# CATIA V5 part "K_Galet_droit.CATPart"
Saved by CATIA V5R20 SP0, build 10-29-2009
Part number: Galet_droit
Bounding box of the stored display mesh (mm): x 0 to 17.955, y -11.571 to 11.571, z -11.571 to 11.571
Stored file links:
  G:\Khaled_CFAO_2011\SIL\SIL_GR2\zthiebault\Khaled\CAD_ThinkMOTION\K_Galet_droit.CATPart
  F:\Projet Thinkmotion\Catia\galet.CATPart
  F:\Projet Thinkmotion\Catia\FINAL\HabillageFinal.CATProduct
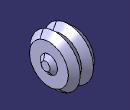
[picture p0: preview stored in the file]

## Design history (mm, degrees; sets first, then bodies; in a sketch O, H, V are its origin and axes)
External parameters (linked from other documents)
  External.Rgaletaucontact = 9 mm
  `External.dist_bâticerclecontactgalet` = 10.41 mm
Set1
  Line1 "Droite_base_galetdroit": linked copy from another document
  Plane1 "Plan_base_galet_cerclecontact": linked copy from another document
Body1 (main body)
  Sketch1 on zx-plane, origin (0, 0, 0), H (-1, 0, 0), V (0, 0, 1)
    line L1 (0, 0) -> (-17.9551, 0)
    line L2 (-17.9551, 0) -> (-17.9551, -2)
    line L3 (-17.9551, -2) -> (-16.41, -3.9654)
    point P4 (-16.41, -3.9654)
    line L4 (-16.41, -3.9654) -> (-16.41, -8.9654)
    line L5 (-16.41, -8.9654) -> (-13.4742, -11.5712)
    line L6 (-13.4742, -11.5712) -> (-10.41, -9)
    point P7 (-10.41, -9)
    line L7 (-10.41, -9) -> (-7.3458, -11.5712)
    line L8 (-7.3458, -11.5712) -> (-4.41, -9)
    line L9 (-4.41, -9) -> (-4.41, -3)
    line L10 (-4.41, -3) -> (-1.3229, -3)
    line L11 (-1.3229, -3) -> (0, -1.5)
    line L12 (0, -1.5) -> (0, 0)
    construction line L13 (-13.4742, -11.5712) -> (-7.3458, -11.5712)
    axis line L14 (-4.41, -9) -> (-10.41, -9)
    reference intersected line E1 through (-10.41, 0) direction (0, -1) from Plane1
    reference projected line E2 (0, 0) -> (-10.41, 0) from Line1
    length L2 = 2
    length L4 = 5
    angle L6 L7 = 100
    length L6 = 4
    length L7 = 4 {= Sketch1.length(L6)}
    length L9 = 6
    length L11 = 2
    distance L1 P7 = 9 {= External.Rgaletaucontact}
    distance L4 P7 = 6
    length L12 = 1.5
    distance L12 P7 = 10.41 {= `External.dist_bâticerclecontactgalet`}
    distance L9 P7 = 6 {= Sketch1.distance(L4 P7)}
    length L3 = 2.5
    horizontal: L1 H, L10 H, L13 H, L14 H
    vertical: L2 V, L4 V, L9 V, L12 V
    coincidence: L7 P4, E1 P7, L1 E2
  Shaft1: profile Sketch1, axis Sketch1.L1, angle 360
